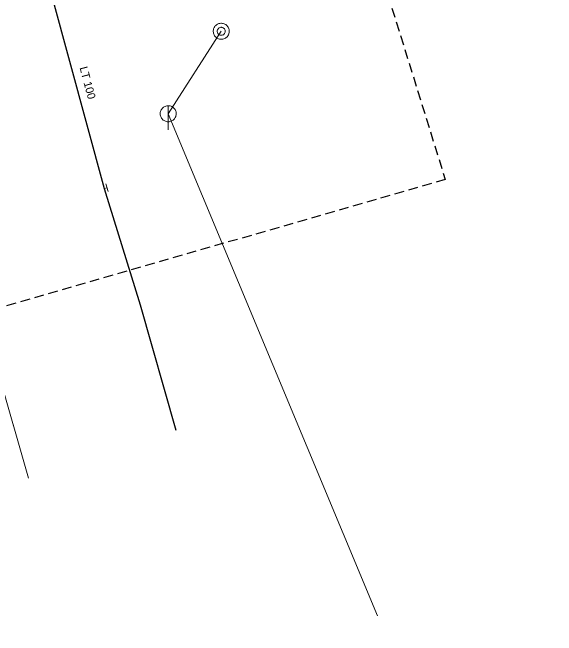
# Model space of a CAD drawing. Extents: x -690254 to -689100, y -975264 to -974703.
# Drawn here: x -689647.1 to -689579.1, y -975127.6 to -975049.8 of the extents above; entities that cross this region are included whole.
import ezdxf

# ---------------------------------------------------------------- set-up
doc = ezdxf.new("R2010")
doc.units = 0
doc.header["$LTSCALE"] = 0.4
doc.linetypes.add('MEDIUM_DASHED', pattern=[4.5, 3, -1.5])
for name, color, linetype, lineweight in [('1', 7, 'Continuous', 13), ('11', 7, 'Continuous', 13), ('14', 7, 'Continuous', 13), ('17', 7, 'Continuous', 25), ('22', 7, 'Continuous', 13), ('34', 7, 'Continuous', 13), ('63', 7, 'MEDIUM_DASHED', 25)]:
    doc.layers.add(name, color=color, linetype=linetype, lineweight=lineweight)

msp = doc.modelspace()

# ---------------------------------------------------------------- linework, layer by layer
at = {"layer": '11'}
msp.add_line((-689653.911, -975077.2), (-689645.095, -975107.972), dxfattribs=at)
msp.add_lwpolyline([(-689621.006, -975052.173), (-689627.632, -975062.464), (-689601.514, -975125.167)], dxfattribs=at)
at = {"layer": '14'}
msp.add_line((-689635.641, -975071.81), (-689635.27, -975071.71), dxfattribs=at)
at = {"layer": '17'}
msp.add_lwpolyline([(-689644.013, -975040.294), (-689643.761, -975041.024), (-689642.109, -975047.93), (-689635.641, -975071.81), (-689631.112, -975086.326), (-689626.67, -975101.98)], dxfattribs=at)
at = {"layer": '22'}
msp.add_line((-689627.632, -975064.464), (-689627.631, -975061.464), dxfattribs=at)
for points in [[(-689620.006, -975052.173), (-689620.012, -975052.064), (-689620.03, -975051.956), (-689620.06, -975051.85), (-689620.1, -975051.749), (-689620.152, -975051.652), (-689620.214, -975051.562), (-689620.286, -975051.479), (-689620.366, -975051.405), (-689620.454, -975051.339), (-689620.548, -975051.284), (-689620.648, -975051.239), (-689620.753, -975051.206), (-689620.86, -975051.184), (-689620.969, -975051.174), (-689621.079, -975051.176), (-689621.187, -975051.19), (-689621.294, -975051.215), (-689621.397, -975051.252), (-689621.495, -975051.301), (-689621.587, -975051.359), (-689621.673, -975051.428), (-689621.75, -975051.505), (-689621.819, -975051.591), (-689621.878, -975051.683), (-689621.926, -975051.781), (-689621.963, -975051.884), (-689621.989, -975051.991), (-689622.003, -975052.099), (-689622.005, -975052.209), (-689621.995, -975052.318), (-689621.974, -975052.425), (-689621.94, -975052.529), (-689621.896, -975052.629), (-689621.841, -975052.724), (-689621.775, -975052.812), (-689621.701, -975052.892), (-689621.618, -975052.964), (-689621.528, -975053.026), (-689621.432, -975053.078), (-689621.33, -975053.119), (-689621.225, -975053.149), (-689621.117, -975053.167), (-689621.007, -975053.173), (-689620.898, -975053.167), (-689620.79, -975053.149), (-689620.685, -975053.12), (-689620.583, -975053.079), (-689620.486, -975053.027), (-689620.396, -975052.965), (-689620.313, -975052.894), (-689620.238, -975052.814), (-689620.173, -975052.726), (-689620.117, -975052.632), (-689620.073, -975052.532), (-689620.039, -975052.428), (-689620.017, -975052.32), (-689620.007, -975052.211)], [(-689620.506, -975052.173), (-689620.512, -975052.096), (-689620.53, -975052.021), (-689620.559, -975051.949), (-689620.599, -975051.883), (-689620.649, -975051.823), (-689620.707, -975051.772), (-689620.772, -975051.731), (-689620.843, -975051.7), (-689620.918, -975051.681), (-689620.995, -975051.673), (-689621.073, -975051.677), (-689621.148, -975051.694), (-689621.221, -975051.721), (-689621.288, -975051.76), (-689621.348, -975051.808), (-689621.4, -975051.866), (-689621.443, -975051.93), (-689621.475, -975052), (-689621.496, -975052.075), (-689621.506, -975052.152), (-689621.503, -975052.229), (-689621.488, -975052.305), (-689621.462, -975052.378), (-689621.425, -975052.446), (-689621.378, -975052.507), (-689621.322, -975052.561), (-689621.258, -975052.605), (-689621.188, -975052.639), (-689621.114, -975052.661), (-689621.038, -975052.672), (-689620.96, -975052.671), (-689620.884, -975052.658), (-689620.811, -975052.633), (-689620.742, -975052.598), (-689620.68, -975052.552), (-689620.625, -975052.497), (-689620.58, -975052.434), (-689620.544, -975052.365), (-689620.52, -975052.292), (-689620.508, -975052.215)], [(-689626.632, -975062.464), (-689626.637, -975062.355), (-689626.655, -975062.247), (-689626.685, -975062.141), (-689626.725, -975062.04), (-689626.777, -975061.943), (-689626.839, -975061.853), (-689626.911, -975061.77), (-689626.991, -975061.696), (-689627.079, -975061.63), (-689627.173, -975061.575), (-689627.273, -975061.53), (-689627.378, -975061.497), (-689627.485, -975061.475), (-689627.594, -975061.465), (-689627.704, -975061.467), (-689627.812, -975061.481), (-689627.919, -975061.506), (-689628.022, -975061.543), (-689628.12, -975061.592), (-689628.212, -975061.65), (-689628.298, -975061.719), (-689628.375, -975061.796), (-689628.444, -975061.882), (-689628.503, -975061.974), (-689628.551, -975062.072), (-689628.588, -975062.175), (-689628.614, -975062.282), (-689628.628, -975062.39), (-689628.631, -975062.5), (-689628.621, -975062.609), (-689628.6, -975062.716), (-689628.566, -975062.82), (-689628.522, -975062.92), (-689628.467, -975063.015), (-689628.401, -975063.103), (-689628.327, -975063.183), (-689628.244, -975063.255), (-689628.154, -975063.317), (-689628.058, -975063.369), (-689627.956, -975063.41), (-689627.851, -975063.44), (-689627.743, -975063.458), (-689627.633, -975063.464), (-689627.524, -975063.458), (-689627.416, -975063.44), (-689627.311, -975063.411), (-689627.209, -975063.37), (-689627.112, -975063.318), (-689627.022, -975063.256), (-689626.939, -975063.185), (-689626.864, -975063.105), (-689626.799, -975063.017), (-689626.743, -975062.923), (-689626.699, -975062.823), (-689626.665, -975062.719), (-689626.643, -975062.611), (-689626.633, -975062.502)]]:
    msp.add_lwpolyline(points, close=True, dxfattribs=at)
at = {"layer": '34'}
msp.add_line((-689635.401, -975071.227), (-689635.139, -975072.192), dxfattribs=at)
at = {"layer": '63'}
msp.add_lwpolyline([(-690175.832, -975238.167), (-690201.511, -975156.663), (-690201.511, -975156.663), (-689696.859, -975008.171), (-689696.859, -975008.171), (-689730.354, -974917.735), (-689730.354, -974917.735), (-689127.452, -974763.66), (-689127.452, -974763.66), (-689118.52, -974838.465), (-689118.52, -974838.465), (-689624.288, -974970.21), (-689624.288, -974970.21), (-689593.026, -975070.694), (-689593.026, -975070.694)], close=True, dxfattribs=at)

# ---------------------------------------------------------------- texts
at = {"layer": '1'}
msp.add_text('LT 100', height=1, rotation=285, dxfattribs=at).set_placement((-689638.708, -975056.716))

doc.saveas('drawing.dxf')
